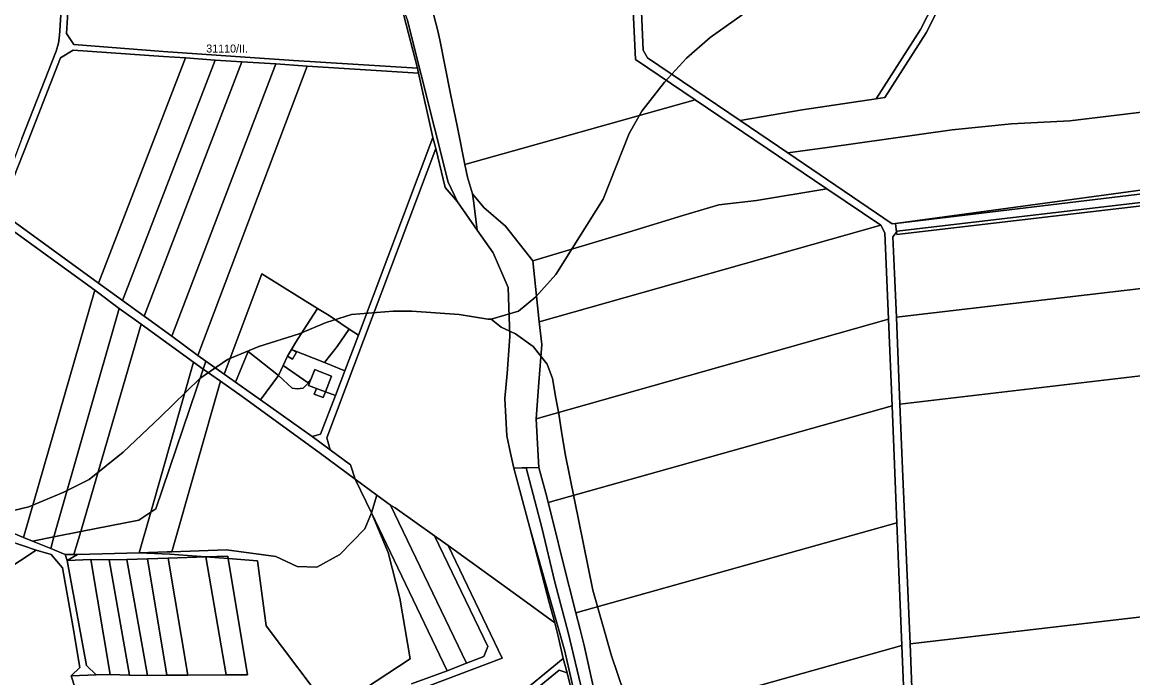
# Model space of a CAD drawing. Extents: x -541351 to -537540, y -1162694 to -1159725.
# Drawn here: x -539563 to -538870, y -1161934 to -1161525 of the extents above; entities that cross this region are included whole.
import ezdxf

# ---------------------------------------------------------------- set-up
doc = ezdxf.new("R2010")
doc.units = 0
for name, color, linetype in [('95560013', 7, 'Continuous'), ('95590013', 7, 'Continuous'), ('95600013', 7, 'Continuous'), ('95610013', 7, 'Continuous'), ('95620013', 7, 'Continuous'), ('95640013', 7, 'Continuous'), ('95660013', 7, 'Continuous')]:
    doc.layers.add(name, color=color, linetype=linetype)

msp = doc.modelspace()

# ---------------------------------------------------------------- linework, layer by layer
at = {"layer": '95560013'}
for points in [[(-539533.39, -1161367.17), (-539528.83, -1161372.95), (-539537.3, -1161491.19), (-539540.03, -1161532.85), (-539540.59, -1161537.62), (-539542.08, -1161542.6), (-539563.48, -1161597.18), (-539577.88, -1161634.94), (-539584.99, -1161637.27), (-539619.67, -1161612.02), (-539611.41, -1161487.28), (-539603.07, -1161362.24)], [(-539535.76, -1161531.54), (-539533.06, -1161491.37), (-539524.83, -1161373.04), (-539519.3, -1161368.27), (-539443.35, -1161373.22), (-539386.7, -1161377.26), (-539364.89, -1161419.69), (-539325.02, -1161520.27), (-539316.47, -1161553.16), (-539393.88, -1161548.37), (-539475.24, -1161542.78), (-539531.17, -1161538.46)], [(-539165.77, -1161475.73), (-539118.49, -1161469.02), (-539078.91, -1161461.6), (-539033.77, -1161454.46), (-538967.29, -1161445.36), (-538990.03, -1161504.88), (-539002.3, -1161529.1), (-539029.85, -1161572.32), (-539076.14, -1161579.22), (-539114.95, -1161586), (-539172.72, -1161546.83), (-539175.52, -1161542.03), (-539178.27, -1161479.78), (-539175.58, -1161477.66)], [(-539303.69, -1161529.93), (-539307.78, -1161514.67), (-539271.36, -1161497.96), (-539253.99, -1161490.48), (-539238.57, -1161485.84), (-539214.9, -1161480.72), (-539196.33, -1161478.48), (-539183.57, -1161477.43), (-539180.21, -1161547.75), (-539143.02, -1161572.92), (-539286.85, -1161613.44), (-539291.53, -1161590.26), (-539295.77, -1161569.23), (-539302.55, -1161535.61)], [(-539539.4, -1161546.84), (-539531.55, -1161541.95), (-539474.99, -1161545.97), (-539461.37, -1161546.78), (-539515.68, -1161687.42), (-539572.36, -1161646.34), (-539574.86, -1161637.02), (-539559.61, -1161598.65)], [(-539500.69, -1161698.34), (-539515.68, -1161687.42), (-539461.37, -1161546.78), (-539442.88, -1161548.27)], [(-539442.88, -1161548.27), (-539426.21, -1161549.25), (-539487.2, -1161708.11), (-539500.69, -1161698.34)], [(-539484.15, -1161710.2), (-539487.2, -1161708.11), (-539426.21, -1161549.25), (-539404.89, -1161550.53), (-539469.92, -1161720.56)], [(-539453.71, -1161732.53), (-539469.92, -1161720.56), (-539404.89, -1161550.53), (-539393.62, -1161551.32), (-539385.35, -1161551.95)], [(-539413.6, -1161681.54), (-539437.27, -1161744.18), (-539448.59, -1161736.16), (-539453.71, -1161732.53), (-539385.35, -1161551.95), (-539315.76, -1161556.43), (-539306.78, -1161596.54), (-539353.29, -1161719.96), (-539359.12, -1161716.15), (-539360.62, -1161715.05), (-539360.91, -1161714.86), (-539371.51, -1161707.71), (-539378.9, -1161703.23)], [(-538982.39, -1161591.84), (-538945.39, -1161587.98), (-538909.04, -1161586.11), (-538744.9, -1161566.45), (-538797.48, -1161620.29), (-539017.95, -1161650.26), (-539019.85, -1161650.49), (-539085.19, -1161606.18), (-539060.53, -1161602.73)], [(-539128.23, -1161638.48), (-539150.67, -1161645.11), (-539184.55, -1161655.72), (-539244.42, -1161673.52), (-539261.46, -1161651.91), (-539275.02, -1161640.13), (-539281.97, -1161631.64), (-539285.25, -1161621.38), (-539286.85, -1161613.44), (-539143.02, -1161572.92), (-539060.78, -1161628.57), (-539104.58, -1161635.85)], [(-539341.82, -1161819.88), (-539355.34, -1161809.82), (-539358.35, -1161800.84), (-539371.01, -1161791.56), (-539373.09, -1161783.93), (-539305.07, -1161603.34), (-539299.04, -1161627.81), (-539291.45, -1161636.72), (-539279.15, -1161654.33), (-539269.09, -1161668.45), (-539259.73, -1161690.18), (-539258.67, -1161720.64), (-539260.49, -1161743.77), (-539261.83, -1161759.51), (-539260.63, -1161782.68), (-539258.35, -1161793.49), (-539256.35, -1161802.83), (-539246.32, -1161840.14), (-539234.16, -1161886.78), (-539230.64, -1161899.55), (-539252.92, -1161883.34), (-539297.23, -1161851.16), (-539305.82, -1161845.08), (-539330.29, -1161827.74), (-539333.23, -1161826.06)], [(-539184.55, -1161655.72), (-539150.67, -1161645.11), (-539128.23, -1161638.48), (-539104.58, -1161635.85), (-539060.78, -1161628.57), (-539027.11, -1161651.35), (-539240.34, -1161711.55), (-539244.42, -1161673.52)], [(-539017.01, -1161657.17), (-538798.31, -1161631.51), (-538800.12, -1161655.85), (-538802.17, -1161683.57), (-539017.32, -1161708.72), (-539018.5, -1161681.44), (-539019.5, -1161658.47), (-539017.23, -1161655.55)], [(-539518.02, -1161691.87), (-539562.42, -1161846.2), (-539578.2, -1161839.8), (-539591.16, -1161833.38), (-539621.96, -1161816.51), (-539625.05, -1161809.15), (-539580.04, -1161652.57), (-539574.73, -1161650.57)], [(-539240.34, -1161711.55), (-539027.11, -1161651.35), (-539024.51, -1161655.96), (-539022.27, -1161709.92), (-539242.37, -1161772.11), (-539240.64, -1161749.54), (-539238.81, -1161725.75)], [(-539017.32, -1161708.72), (-538802.17, -1161683.57), (-538806.25, -1161738.46), (-539015.15, -1161763.02)], [(-539518.02, -1161691.87), (-539502.73, -1161703.19), (-539543.48, -1161845.82), (-539556.8, -1161848.47), (-539562.42, -1161846.2)], [(-539543.48, -1161845.82), (-539502.73, -1161703.19), (-539489.01, -1161713.04), (-539526.81, -1161842.51)], [(-539022.27, -1161709.92), (-539020.03, -1161764.07), (-539234.86, -1161824.29), (-539235.74, -1161820.78), (-539240.72, -1161802.49), (-539241.52, -1161787.71), (-539242.37, -1161772.11)], [(-539490.54, -1161835.31), (-539526.81, -1161842.51), (-539489.01, -1161713.04), (-539486.7, -1161714.62), (-539456.27, -1161736.86), (-539483.09, -1161830.42)], [(-539450.22, -1161741.11), (-539479.9, -1161828.33), (-539483.09, -1161830.42), (-539456.27, -1161736.86)], [(-539008.79, -1161912.59), (-539013.47, -1161803.39), (-539015.15, -1161763.02), (-538806.25, -1161738.46), (-538810.43, -1161794.77), (-538817.52, -1161890.24)], [(-539384.97, -1161750.01), (-539384.62, -1161749.58), (-539383.06, -1161747.64), (-539384.54, -1161751.31), (-539379.47, -1161753.11), (-539380.88, -1161756.78), (-539375.31, -1161758.91), (-539373.88, -1161755.32), (-539367.57, -1161757.57), (-539377.06, -1161781.74), (-539382.26, -1161783.08), (-539414.57, -1161760.24), (-539403.27, -1161745.18), (-539394.73, -1161753.05), (-539391.64, -1161753.43), (-539387.8, -1161752.93)], [(-539017.01, -1161837.1), (-539217.45, -1161893.33), (-539225.57, -1161861.14), (-539231.34, -1161838.25), (-539234.86, -1161824.29), (-539020.03, -1161764.07)], [(-539355.34, -1161809.82), (-539341.82, -1161819.88), (-539345.14, -1161830.84)], [(-539212.32, -1161913.69), (-539214.84, -1161903.7), (-539217.45, -1161893.33), (-539017.01, -1161837.1), (-539013.85, -1161913.55), (-539200.6, -1161966.02), (-539206.22, -1161940.94)], [(-539490.37, -1161855.82), (-539471.15, -1161856.57), (-539448.61, -1161858.31), (-539472.1, -1161859.02), (-539485.17, -1161859.45), (-539497.96, -1161859.87), (-539509.04, -1161860.23), (-539520.5, -1161859.91), (-539535.16, -1161860.62), (-539528.75, -1161856.77)], [(-539343.33, -1161952.72), (-539318.07, -1161942.05), (-539263.6, -1161921.58), (-539297.23, -1161851.16), (-539252.92, -1161883.34), (-539230.64, -1161899.55), (-539228.65, -1161907.73), (-539225.42, -1161921.81), (-539256.95, -1161947.48), (-539303.31, -1161984.78), (-539352.24, -1162024.23), (-539400.34, -1162062.78), (-539437.95, -1162093.1), (-539473.3, -1162058.96), (-539471.82, -1162050.32), (-539426.23, -1162014.21), (-539369.01, -1161968.59)], [(-539496.39, -1161932.17), (-539508.43, -1161931.66), (-539520.5, -1161859.91), (-539509.04, -1161860.23)], [(-539485.13, -1161932.37), (-539496.39, -1161932.17), (-539509.04, -1161860.23), (-539497.96, -1161859.87)], [(-539497.96, -1161859.87), (-539485.17, -1161859.45), (-539472.91, -1161932.14), (-539485.13, -1161932.37)], [(-539435.98, -1161931.99), (-539459.79, -1161932.14), (-539472.1, -1161859.02), (-539448.61, -1161858.31)], [(-539422.7, -1161931.99), (-539424.46, -1161931.99), (-539435.98, -1161931.99), (-539448.61, -1161858.31), (-539434.71, -1161859.39)], [(-539007.14, -1161951.05), (-539008.79, -1161912.59), (-538817.52, -1161890.24), (-538820.83, -1161934.92), (-539006.92, -1161956.95)], [(-539197.76, -1161978.7), (-539200.6, -1161966.02), (-539013.85, -1161913.55), (-539010.53, -1161993.75), (-539184.9, -1162042.56), (-539186.67, -1162034.94), (-539187.18, -1162032.19), (-539193.59, -1161997.34)], [(-539300.91, -1161987.96), (-539311.92, -1161997.05), (-539330.17, -1162011.43), (-539349.64, -1162027.3), (-539360.06, -1162035.62), (-539369.27, -1162043.08), (-539378.58, -1162050.4), (-539387.72, -1162057.87), (-539397.54, -1162065.69), (-539406.31, -1162072.59), (-539415.18, -1162079.79), (-539425.38, -1162087.75), (-539435.62, -1162095.01), (-539437.95, -1162093.1), (-539400.34, -1162062.78), (-539352.24, -1162024.23), (-539303.31, -1161984.78), (-539256.95, -1161947.48), (-539225.42, -1161921.81), (-539222.91, -1161930.72), (-539227.91, -1161929.12), (-539254.38, -1161950.7)], [(-539210.77, -1161982.93), (-539200.52, -1162034.32), (-539194.04, -1162072.72), (-539188.8, -1162087.6), (-539180.01, -1162104.01), (-539166.2, -1162134.06), (-539158.34, -1162150.83), (-539311.92, -1161997.05), (-539300.91, -1161987.96), (-539254.38, -1161950.7), (-539227.91, -1161929.12), (-539222.91, -1161930.72), (-539219.35, -1161944.98)]]:
    msp.add_lwpolyline(points, close=True, dxfattribs=at)
for points in [[(-538744.9, -1161566.45), (-538909.04, -1161586.11), (-538945.39, -1161587.98), (-538982.39, -1161591.84), (-539060.53, -1161602.73), (-539085.19, -1161606.18), (-539114.95, -1161586), (-539076.14, -1161579.22), (-539029.85, -1161572.32), (-539024.51, -1161571.52), (-538998.73, -1161531.09), (-538986.28, -1161506.51), (-538962.68, -1161444.73), (-538961.19, -1161440.84), (-538900.02, -1161436.5), (-538846.86, -1161433.5)], [(-539010.53, -1161993.75), (-539013.85, -1161913.55), (-539017.01, -1161837.1), (-539020.03, -1161764.07), (-539022.27, -1161709.92), (-539024.51, -1161655.96), (-539027.11, -1161651.35), (-539060.78, -1161628.57), (-539143.02, -1161572.92), (-539180.21, -1161547.75), (-539183.57, -1161477.43)], [(-539178.27, -1161479.78), (-539175.52, -1161542.03), (-539172.72, -1161546.83), (-539114.95, -1161586), (-539085.19, -1161606.18), (-539019.85, -1161650.49), (-539017.95, -1161650.26), (-539017.23, -1161655.55), (-539019.5, -1161658.47), (-539018.5, -1161681.44), (-539017.32, -1161708.72), (-539015.15, -1161763.02), (-539013.47, -1161803.39), (-539008.79, -1161912.59), (-539007.14, -1161951.05)], [(-539533.06, -1161491.37), (-539535.76, -1161531.54), (-539531.17, -1161538.46), (-539475.24, -1161542.78), (-539393.88, -1161548.37), (-539316.47, -1161553.16), (-539315.76, -1161556.43), (-539385.35, -1161551.95), (-539393.62, -1161551.32), (-539404.89, -1161550.53), (-539426.21, -1161549.25), (-539442.88, -1161548.27), (-539461.37, -1161546.78), (-539474.99, -1161545.97), (-539531.55, -1161541.95), (-539539.4, -1161546.84), (-539559.61, -1161598.65), (-539574.86, -1161637.02)], [(-539563.48, -1161597.18), (-539542.08, -1161542.6), (-539540.59, -1161537.62), (-539540.03, -1161532.85), (-539537.3, -1161491.19)], [(-538986.28, -1161506.51), (-538998.73, -1161531.09), (-539024.51, -1161571.52), (-539029.85, -1161572.32), (-539002.3, -1161529.1), (-538990.03, -1161504.88)], [(-539572.36, -1161646.34), (-539515.68, -1161687.42), (-539500.69, -1161698.34), (-539487.2, -1161708.11), (-539484.15, -1161710.2), (-539469.92, -1161720.56), (-539453.71, -1161732.53), (-539448.59, -1161736.16), (-539450.22, -1161741.11), (-539456.27, -1161736.86), (-539486.7, -1161714.62), (-539489.01, -1161713.04), (-539502.73, -1161703.19), (-539518.02, -1161691.87), (-539574.73, -1161650.57)], [(-539527.87, -1161947.38), (-539532.84, -1161932.62), (-539517.03, -1161931.97), (-539508.43, -1161931.66), (-539496.39, -1161932.17), (-539485.13, -1161932.37), (-539472.91, -1161932.14), (-539459.79, -1161932.14), (-539435.98, -1161931.99), (-539424.46, -1161931.99), (-539422.7, -1161931.99), (-539434.71, -1161859.39), (-539416.41, -1161860.82), (-539411.01, -1161901.38), (-539370.71, -1161954.54), (-539320.94, -1161921.88), (-539327.48, -1161884.12), (-539334.65, -1161855.61), (-539345.14, -1161830.84), (-539297.92, -1161929.45), (-539320.22, -1161937.6)], [(-539320.22, -1161937.6), (-539297.92, -1161929.45), (-539285.73, -1161924.59), (-539274.99, -1161920.44), (-539272.55, -1161914.21), (-539305.82, -1161845.08), (-539297.23, -1161851.16), (-539263.6, -1161921.58), (-539318.07, -1161942.05)]]:
    msp.add_lwpolyline(points, dxfattribs=at)
at = {"layer": '95590013'}
msp.add_lwpolyline([(-539508.43, -1161931.66), (-539517.03, -1161931.97), (-539523.09, -1161926.07), (-539535.16, -1161860.62), (-539520.5, -1161859.91)], close=True, dxfattribs=at)
at = {"layer": '95600013'}
for points in [[(-539479.9, -1161828.33), (-539450.22, -1161741.11), (-539439.41, -1161748.71), (-539469.96, -1161855.26), (-539472.81, -1161855.26), (-539490.37, -1161855.82), (-539483.09, -1161830.42)], [(-539391.68, -1161864.38), (-539404.93, -1161857.98), (-539435.74, -1161853.86), (-539469.96, -1161855.26), (-539439.41, -1161748.71), (-539426, -1161758.14), (-539376.97, -1161793.72), (-539355.34, -1161809.82), (-539345.14, -1161830.84), (-539349.38, -1161840.87), (-539364.84, -1161856.72), (-539379.32, -1161864.7)], [(-539530.99, -1161856.83), (-539526.81, -1161842.51), (-539490.54, -1161835.31), (-539483.09, -1161830.42), (-539490.37, -1161855.82), (-539528.75, -1161856.77)], [(-539416.41, -1161860.82), (-539434.71, -1161859.39), (-539434.97, -1161857.81), (-539448.61, -1161858.31), (-539471.15, -1161856.57), (-539490.37, -1161855.82), (-539472.81, -1161855.26), (-539469.96, -1161855.26), (-539435.74, -1161853.86), (-539404.93, -1161857.98), (-539391.68, -1161864.38), (-539379.32, -1161864.7), (-539364.84, -1161856.72), (-539349.38, -1161840.87), (-539345.14, -1161830.84), (-539334.65, -1161855.61), (-539327.48, -1161884.12), (-539320.94, -1161921.88), (-539370.71, -1161954.54), (-539411.01, -1161901.38)], [(-539543.48, -1161845.82), (-539526.81, -1161842.51), (-539530.99, -1161856.83), (-539536.48, -1161856.9), (-539545.54, -1161853.03)], [(-539556.8, -1161848.47), (-539543.48, -1161845.82), (-539545.54, -1161853.03)], [(-539536.48, -1161856.9), (-539530.99, -1161856.83), (-539528.75, -1161856.77), (-539535.16, -1161860.62)], [(-539434.97, -1161857.81), (-539434.71, -1161859.39), (-539448.61, -1161858.31)]]:
    msp.add_lwpolyline(points, close=True, dxfattribs=at)
at = {"layer": '95610013'}
for points in [[(-539430.1, -1161749.19), (-539422.09, -1161730.19), (-539403.27, -1161745.18), (-539414.57, -1161760.24), (-539423.02, -1161754.26)], [(-539297.92, -1161929.45), (-539345.14, -1161830.84), (-539341.82, -1161819.88), (-539333.23, -1161826.06), (-539285.73, -1161924.59)], [(-539305.82, -1161845.08), (-539272.55, -1161914.21), (-539274.99, -1161920.44), (-539285.73, -1161924.59), (-539333.23, -1161826.06), (-539330.29, -1161827.74)], [(-539459.79, -1161932.14), (-539472.91, -1161932.14), (-539485.17, -1161859.45), (-539472.1, -1161859.02)]]:
    msp.add_lwpolyline(points, close=True, dxfattribs=at)
at = {"layer": '95620013'}
msp.add_lwpolyline([(-539636.12, -1161907.82), (-539639.17, -1161904.22), (-539615.14, -1161871.21), (-539592.43, -1161840.03), (-539580.36, -1161845.31), (-539554.51, -1161854.21)], close=True, dxfattribs=at)
msp.add_lwpolyline([(-539609.42, -1161938.46), (-539621.4, -1161931.95), (-539628.15, -1161928.08), (-539633.45, -1161922.3), (-539634.39, -1161919.41), (-539636.12, -1161907.82), (-539554.51, -1161854.21), (-539545.25, -1161856.85), (-539538.16, -1161865.08), (-539531.79, -1161901.38), (-539527.33, -1161927.46), (-539532.84, -1161932.62), (-539527.87, -1161947.38)], dxfattribs=at)
at = {"layer": '95640013'}
for points in [[(-539306.78, -1161596.54), (-539315.76, -1161556.43), (-539316.47, -1161553.16), (-539325.02, -1161520.27), (-539364.89, -1161419.69), (-539386.7, -1161377.26), (-539392.4, -1161365.24), (-539372.91, -1161399.14), (-539356.24, -1161433.35), (-539322.59, -1161523.59), (-539297.21, -1161624.42), (-539291.45, -1161636.72), (-539299.04, -1161627.81), (-539305.07, -1161603.34)], [(-539306.78, -1161596.54), (-539305.07, -1161603.34), (-539373.09, -1161783.93), (-539371.01, -1161791.56), (-539382.26, -1161783.08), (-539377.06, -1161781.74), (-539367.57, -1161757.57), (-539361.86, -1161742.26), (-539353.29, -1161719.96)], [(-538801.32, -1161624.22), (-539017.95, -1161650.26), (-538797.48, -1161620.29)], [(-538797.48, -1161620.29), (-538798.31, -1161631.51), (-538801.13, -1161629.63), (-539016.74, -1161654.92), (-539017.23, -1161655.55), (-539017.95, -1161650.26), (-538801.32, -1161624.22)], [(-539240.34, -1161711.55), (-539238.81, -1161725.75), (-539240.64, -1161749.54), (-539242.37, -1161772.11), (-539241.52, -1161787.71), (-539240.72, -1161802.49), (-539248.53, -1161802.66), (-539251.17, -1161802.72), (-539256.35, -1161802.83), (-539258.35, -1161793.49), (-539260.63, -1161782.68), (-539261.83, -1161759.51), (-539260.49, -1161743.77), (-539258.67, -1161720.64), (-539259.73, -1161690.18), (-539269.09, -1161668.45), (-539279.15, -1161654.33), (-539279.79, -1161649.14), (-539281.42, -1161636.08), (-539281.97, -1161631.64), (-539275.02, -1161640.13), (-539261.46, -1161651.91), (-539244.42, -1161673.52)], [(-538801.13, -1161629.63), (-538798.31, -1161631.51), (-539017.01, -1161657.17), (-539017.23, -1161655.55), (-539016.74, -1161654.92)], [(-539430.1, -1161749.19), (-539437.27, -1161744.18), (-539413.6, -1161681.54), (-539378.9, -1161703.23), (-539387.58, -1161716.88), (-539392.51, -1161724.29), (-539395.12, -1161728.84), (-539397.57, -1161733.03), (-539400.32, -1161738.89), (-539403.27, -1161745.18), (-539422.09, -1161730.19)], [(-539359.23, -1161716.31), (-539366.55, -1161727.08), (-539374.56, -1161737.05), (-539395.12, -1161728.84), (-539392.51, -1161724.29), (-539387.58, -1161716.88), (-539378.9, -1161703.23), (-539371.51, -1161707.71), (-539360.91, -1161714.86), (-539360.62, -1161715.05), (-539359.12, -1161716.15)], [(-539361.86, -1161742.26), (-539374.56, -1161737.05), (-539366.55, -1161727.08), (-539359.23, -1161716.31), (-539359.12, -1161716.15), (-539353.29, -1161719.96)], [(-539400.32, -1161738.89), (-539397.57, -1161733.03), (-539394.55, -1161734.8), (-539392.1, -1161730.61), (-539395.12, -1161728.84), (-539374.56, -1161737.05), (-539361.86, -1161742.26), (-539367.57, -1161757.57), (-539373.88, -1161755.32), (-539370.19, -1161745.52), (-539378.68, -1161742.18), (-539380.56, -1161741.44), (-539383.06, -1161747.64), (-539384.62, -1161749.58)], [(-539394.55, -1161734.8), (-539397.57, -1161733.03), (-539395.12, -1161728.84), (-539392.1, -1161730.61)], [(-539371.01, -1161791.56), (-539358.35, -1161800.84), (-539355.34, -1161809.82), (-539376.97, -1161793.72), (-539426, -1161758.14), (-539439.41, -1161748.71), (-539450.22, -1161741.11), (-539448.59, -1161736.16), (-539437.27, -1161744.18), (-539430.1, -1161749.19), (-539423.02, -1161754.26), (-539414.57, -1161760.24), (-539382.26, -1161783.08)], [(-539391.64, -1161753.43), (-539394.73, -1161753.05), (-539403.27, -1161745.18), (-539400.32, -1161738.89), (-539384.62, -1161749.58), (-539384.97, -1161750.01), (-539387.8, -1161752.93)], [(-539384.54, -1161751.31), (-539383.06, -1161747.64), (-539380.56, -1161741.44), (-539378.68, -1161742.18), (-539370.19, -1161745.52), (-539373.88, -1161755.32), (-539379.47, -1161753.11)], [(-539373.88, -1161755.32), (-539375.31, -1161758.91), (-539380.88, -1161756.78), (-539379.47, -1161753.11)], [(-539166.43, -1162126.43), (-539182.54, -1162094.64), (-539192.18, -1162068.27), (-539206, -1161997.95), (-539224.46, -1161917.18), (-539246.32, -1161840.14), (-539256.35, -1161802.83), (-539251.17, -1161802.72), (-539248.53, -1161802.66), (-539238.86, -1161839.87), (-539230.73, -1161874.17), (-539222.37, -1161905.58), (-539213.27, -1161942.94), (-539204.57, -1161980.85), (-539194.37, -1162032.7), (-539187.23, -1162069.96), (-539181.96, -1162084.06), (-539174.75, -1162100.35), (-539159.66, -1162129.85), (-539143.64, -1162160.68), (-539141.34, -1162168.63), (-539143.95, -1162169.47), (-539147.29, -1162170.54), (-539149.55, -1162160.22)], [(-539180.01, -1162104.01), (-539188.8, -1162087.6), (-539194.04, -1162072.72), (-539200.52, -1162034.32), (-539210.77, -1161982.93), (-539219.35, -1161944.98), (-539222.91, -1161930.72), (-539225.42, -1161921.81), (-539228.65, -1161907.73), (-539230.64, -1161899.55), (-539234.16, -1161886.78), (-539246.32, -1161840.14), (-539224.46, -1161917.18), (-539206, -1161997.95), (-539192.18, -1162068.27), (-539182.54, -1162094.64), (-539166.43, -1162126.43), (-539149.55, -1162160.22), (-539147.29, -1162170.54), (-539148.72, -1162171), (-539158.34, -1162150.83), (-539166.2, -1162134.06)]]:
    msp.add_lwpolyline(points, close=True, dxfattribs=at)
for points in [[(-539307.78, -1161514.67), (-539303.69, -1161529.93), (-539302.55, -1161535.61), (-539295.77, -1161569.23), (-539291.53, -1161590.26), (-539286.85, -1161613.44), (-539285.25, -1161621.38), (-539281.97, -1161631.64), (-539281.42, -1161636.08), (-539279.79, -1161649.14), (-539279.15, -1161654.33), (-539291.45, -1161636.72), (-539297.21, -1161624.42), (-539322.59, -1161523.59)], [(-539213.27, -1161942.94), (-539222.37, -1161905.58), (-539230.73, -1161874.17), (-539238.86, -1161839.87), (-539248.53, -1161802.66), (-539240.72, -1161802.49), (-539235.74, -1161820.78), (-539234.86, -1161824.29), (-539231.34, -1161838.25), (-539225.57, -1161861.14), (-539217.45, -1161893.33), (-539214.84, -1161903.7), (-539212.32, -1161913.69), (-539206.22, -1161940.94)], [(-539578.2, -1161839.8), (-539562.42, -1161846.2), (-539556.8, -1161848.47), (-539545.54, -1161853.03), (-539536.48, -1161856.9), (-539535.16, -1161860.62), (-539523.09, -1161926.07), (-539517.03, -1161931.97), (-539532.84, -1161932.62), (-539527.33, -1161927.46), (-539531.79, -1161901.38), (-539538.16, -1161865.08), (-539545.25, -1161856.85), (-539554.51, -1161854.21), (-539580.36, -1161845.31)]]:
    msp.add_lwpolyline(points, dxfattribs=at)
at = {"layer": '95660013'}
for points in [[(-539113.69, -1161520), (-539133.62, -1161534), (-539148.37, -1161547), (-539162.12, -1161562), (-539176.31, -1161580), (-539184.31, -1161594), (-539200.37, -1161635), (-539230.12, -1161682), (-539242.5, -1161696), (-539253.31, -1161705), (-539270.31, -1161710), (-539272.5, -1161710), (-539290.31, -1161707), (-539319.87, -1161705), (-539331.62, -1161705), (-539357.62, -1161707), (-539373.37, -1161712), (-539390.37, -1161719), (-539415.62, -1161727), (-539435.12, -1161735), (-539452.31, -1161747), (-539477.19, -1161771), (-539500.37, -1161793), (-539521.5, -1161810), (-539537.31, -1161818), (-539559.19, -1161827), (-539584.62, -1161833)], [(-539179.62, -1161966), (-539195.31, -1161920), (-539206.87, -1161879), (-539224.12, -1161794), (-539226.38, -1161780.11), (-539228.19, -1161769), (-539229.94, -1161759.22), (-539232.12, -1161747), (-539235.37, -1161738), (-539244.12, -1161727), (-539255.31, -1161719), (-539264.12, -1161715), (-539270.31, -1161710), (-539253.31, -1161705), (-539242.5, -1161696), (-539230.12, -1161682), (-539200.37, -1161635), (-539184.31, -1161594), (-539176.31, -1161580), (-539162.12, -1161562), (-539148.37, -1161547), (-539133.62, -1161534), (-539113.69, -1161520)], [(-539584.62, -1161833), (-539559.19, -1161827), (-539537.31, -1161818), (-539521.5, -1161810), (-539500.37, -1161793), (-539477.19, -1161771), (-539452.31, -1161747), (-539435.12, -1161735), (-539415.62, -1161727), (-539390.37, -1161719), (-539373.37, -1161712), (-539357.62, -1161707), (-539331.62, -1161705), (-539319.87, -1161705), (-539290.31, -1161707), (-539272.5, -1161710), (-539270.31, -1161710), (-539264.12, -1161715), (-539255.31, -1161719), (-539244.12, -1161727), (-539235.37, -1161738), (-539232.12, -1161747), (-539229.94, -1161759.22), (-539228.19, -1161769), (-539226.38, -1161780.11), (-539224.12, -1161794), (-539206.87, -1161879), (-539195.31, -1161920), (-539179.62, -1161966)]]:
    msp.add_lwpolyline(points, dxfattribs=at)

# ---------------------------------------------------------------- texts
msp.add_text('31110/II.', height=5, rotation=360, dxfattribs=at).set_placement((-539448.36, -1161543.5))

doc.saveas('drawing.dxf')
